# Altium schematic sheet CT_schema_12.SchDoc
size 147 x 119 mm
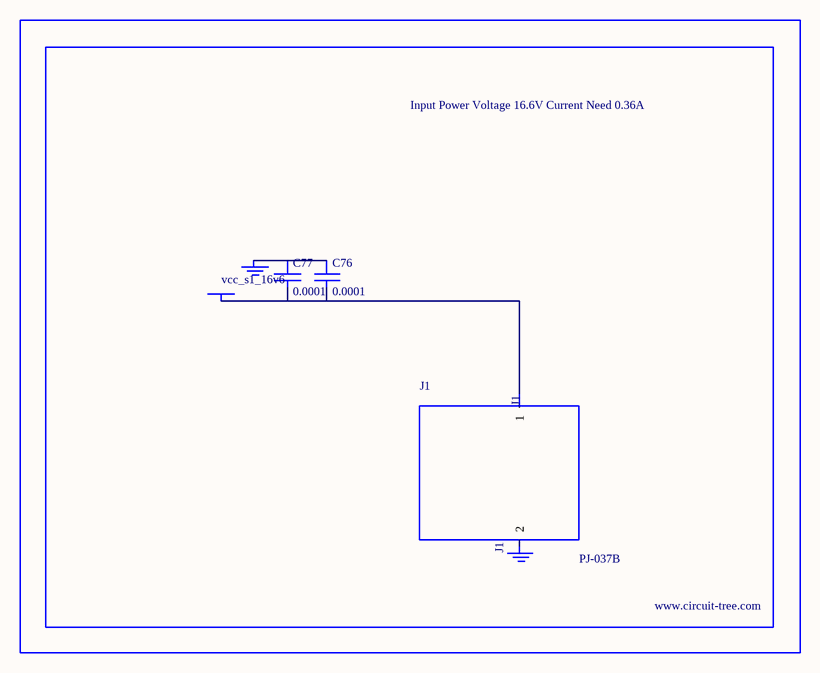
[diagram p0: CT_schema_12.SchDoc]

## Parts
BORDER11  (no value)
C76  0.0001  [EXV-9H]
C77  0.0001  [EXV-9H]
GND_INSTANCE_11_0  (no value)
GND_INSTANCE_11_1  (no value)
J1  PJ-037B  [PJ-037B_PACKAGE]
POWER_INSTANCE_11_0  vcc_s1_16v6

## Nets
NetC76_1: C76.1 C77.1 GND_INSTANCE_11_0.0(GND)
NetC76_2: C76.2 C77.2 J1.1 POWER_INSTANCE_11_0.0(PWR)

Not connected (* = marked no-connect by the designer): GND_INSTANCE_11_1 0(GND); J1 2

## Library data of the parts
BORDER11 = BORDER_PAGE11
C76 C77 = EDK107M035A9HAA
GND_INSTANCE_11_0 GND_INSTANCE_11_1 = GND
POWER_INSTANCE_11_0 = PWR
